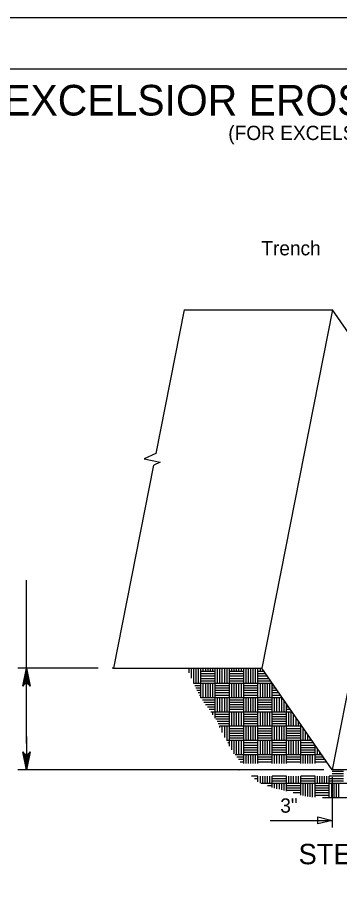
# Model space of a CAD drawing. Extents: x 1083.1 to 1117.1, y 719.4 to 741.4.
# Drawn here: x 1095.42 to 1098.57, y 732.69 to 741.35 of the extents above; entities that cross this region are included whole.
import ezdxf

# ---------------------------------------------------------------- set-up
doc = ezdxf.new("R2010")
doc.units = 0
for name, color, linetype in [('SH_Border', 7, 'Continuous'), ('SH_Cut_Line', 7, 'Continuous'), ('ST_Details', 7, 'Continuous'), ('ST_Text', 7, 'Continuous')]:
    doc.layers.add(name, color=color, linetype=linetype)

msp = doc.modelspace()

# ---------------------------------------------------------------- linework, layer by layer
at = {"layer": 'SH_Border'}
msp.add_lwpolyline([(1085.1264, 740.8541), (1116.6264, 740.8541), (1116.6264, 719.8541), (1085.1264, 719.8541)], close=True, dxfattribs=at)
at = {"layer": 'SH_Cut_Line'}
msp.add_lwpolyline([(1083.1264, 719.3541), (1117.1264, 719.3541), (1117.1264, 741.3541), (1083.1264, 741.3541)], close=True, dxfattribs=at)
at = {"layer": 'ST_Details'}
for p, q in [((1097.0496, 738.4926), (1096.7722, 737.0887)), ((1097.0496, 738.4926), (1098.5056, 738.4926)), ((1098.5056, 738.4926), (1097.8124, 734.9853)), ((1099.0136, 737.7593), (1098.5056, 738.4926)), ((1096.7721, 737.0886), (1096.6583, 737.0335)), ((1096.6576, 737.0352), (1096.8122, 737.0015)), ((1096.8122, 737.0015), (1096.7506, 736.9716)), ((1096.7491, 736.9719), (1096.3564, 734.9853)), ((1095.5022, 734.2481), (1095.5022, 735.846)), ((1098.7149, 735.0666), (1098.5021, 733.9896)), ((1096.2071, 734.9853), (1095.4163, 734.9853)), ((1095.4775, 734.8231), (1095.5022, 734.9853)), ((1095.4878, 734.8293), (1095.5022, 734.9853)), ((1095.5022, 734.8321), (1095.5022, 734.9853)), ((1095.5136, 734.8304), (1095.5022, 734.9853)), ((1095.5246, 734.825), (1095.5022, 734.9853)), ((1096.3564, 734.9853), (1096.3438, 734.9853)), ((1096.3564, 734.9853), (1097.8124, 734.9853)), ((1097.097, 734.9398), (1097.097, 734.9853)), ((1097.1203, 734.8873), (1097.1203, 734.9853)), ((1097.1436, 734.8359), (1097.1436, 734.9853)), ((1097.1669, 734.8359), (1097.1669, 734.9853)), ((1097.1902, 734.8359), (1097.1902, 734.9853)), ((1097.2136, 734.6952), (1097.2136, 734.9853)), ((1097.3535, 734.9524), (1097.2136, 734.9524)), ((1097.3535, 734.9291), (1097.2136, 734.9291)), ((1097.2369, 734.9524), (1097.2369, 734.9853)), ((1097.2602, 734.9524), (1097.2602, 734.9853)), ((1097.2836, 734.9524), (1097.2836, 734.9853)), ((1097.3069, 734.9524), (1097.3069, 734.9853)), ((1097.3301, 734.9524), (1097.3301, 734.9853)), ((1097.3535, 734.4967), (1097.3535, 734.9853)), ((1097.3768, 734.8359), (1097.3768, 734.9758)), ((1097.4001, 734.8359), (1097.4001, 734.9758)), ((1097.4235, 734.8359), (1097.4235, 734.9758)), ((1097.4468, 734.8359), (1097.4468, 734.9758)), ((1097.4701, 734.8359), (1097.4701, 734.9758)), ((1097.4934, 734.222), (1097.4934, 734.9853)), ((1097.6334, 734.9524), (1097.4934, 734.9524)), ((1097.6334, 734.9291), (1097.4934, 734.9291)), ((1097.5167, 734.9524), (1097.5167, 734.9853)), ((1097.5401, 734.9524), (1097.5401, 734.9853)), ((1097.5634, 734.9524), (1097.5634, 734.9853)), ((1097.5867, 734.9524), (1097.5867, 734.9853)), ((1097.6101, 734.9524), (1097.6101, 734.9853)), ((1097.6334, 734.0506), (1097.6334, 734.9853)), ((1097.6567, 734.8359), (1097.6567, 734.9853)), ((1097.68, 734.8359), (1097.68, 734.9853)), ((1097.7033, 734.8359), (1097.7033, 734.9853)), ((1097.7266, 734.8359), (1097.7266, 734.9853)), ((1097.75, 734.8359), (1097.75, 734.9853)), ((1097.7733, 734.0506), (1097.7733, 734.9853)), ((1097.8318, 734.9524), (1097.7733, 734.9524)), ((1097.8479, 734.9291), (1097.7733, 734.9291)), ((1097.7966, 734.9524), (1097.7966, 734.9853)), ((1098.5021, 733.9896), (1097.8124, 734.9853)), ((1097.9126, 734.8359), (1097.1431, 734.8359)), ((1097.3535, 734.9058), (1097.2136, 734.9058)), ((1097.3535, 734.8824), (1097.2136, 734.8824)), ((1097.3535, 734.8591), (1097.2136, 734.8591)), ((1097.2369, 734.7659), (1097.2369, 734.8359)), ((1097.2602, 734.7659), (1097.2602, 734.8359)), ((1097.2836, 734.7659), (1097.2836, 734.8359)), ((1097.3069, 734.7659), (1097.3069, 734.8359)), ((1097.3301, 734.7659), (1097.3301, 734.8359)), ((1097.6334, 734.9058), (1097.4934, 734.9058)), ((1097.6334, 734.8824), (1097.4934, 734.8824)), ((1097.6334, 734.8591), (1097.4934, 734.8591)), ((1097.5167, 734.7659), (1097.5167, 734.8359)), ((1097.5401, 734.7659), (1097.5401, 734.8359)), ((1097.5634, 734.7659), (1097.5634, 734.8359)), ((1097.5867, 734.7659), (1097.5867, 734.8359)), ((1097.6101, 734.7659), (1097.6101, 734.8359)), ((1097.8641, 734.9058), (1097.7733, 734.9058)), ((1097.8802, 734.8824), (1097.7733, 734.8824)), ((1097.8964, 734.8591), (1097.7733, 734.8591)), ((1097.7966, 734.7659), (1097.7966, 734.8359)), ((1097.82, 734.7659), (1097.82, 734.8359)), ((1097.8432, 734.7659), (1097.8432, 734.8359)), ((1097.8666, 734.7659), (1097.8666, 734.8359)), ((1097.8899, 734.7659), (1097.8899, 734.8359)), ((1097.9132, 734.0506), (1097.9132, 734.8349)), ((1097.2136, 734.8125), (1097.1536, 734.8125)), ((1097.2136, 734.7892), (1097.1639, 734.7892)), ((1097.2136, 734.7659), (1097.1743, 734.7659)), ((1097.2136, 734.7425), (1097.1871, 734.7425)), ((1097.2369, 734.6959), (1097.2369, 734.7659)), ((1097.2602, 734.6959), (1097.2602, 734.7659)), ((1097.2836, 734.6959), (1097.2836, 734.7659)), ((1097.3069, 734.6959), (1097.3069, 734.7659)), ((1097.3301, 734.6959), (1097.3301, 734.7659)), ((1097.4235, 734.8125), (1097.3535, 734.8125)), ((1097.4235, 734.7892), (1097.3535, 734.7892)), ((1097.4235, 734.7659), (1097.3535, 734.7659)), ((1097.4235, 734.7425), (1097.3535, 734.7425)), ((1097.4934, 734.8125), (1097.4235, 734.8125)), ((1097.4934, 734.7892), (1097.4235, 734.7892)), ((1097.4934, 734.7659), (1097.4235, 734.7659)), ((1097.4934, 734.7425), (1097.4235, 734.7425)), ((1097.5167, 734.6959), (1097.5167, 734.7659)), ((1097.5401, 734.6959), (1097.5401, 734.7659)), ((1097.5634, 734.6959), (1097.5634, 734.7659)), ((1097.5867, 734.6959), (1097.5867, 734.7659)), ((1097.6101, 734.6959), (1097.6101, 734.7659)), ((1097.7033, 734.8125), (1097.6334, 734.8125)), ((1097.7033, 734.7892), (1097.6334, 734.7892)), ((1097.7033, 734.7659), (1097.6334, 734.7659)), ((1097.7033, 734.7425), (1097.6334, 734.7425)), ((1097.7733, 734.8125), (1097.7033, 734.8125)), ((1097.7733, 734.7892), (1097.7033, 734.7892)), ((1097.7733, 734.7659), (1097.7033, 734.7659)), ((1097.7733, 734.7425), (1097.7033, 734.7425)), ((1097.7966, 734.6959), (1097.7966, 734.7659)), ((1097.82, 734.6959), (1097.82, 734.7659)), ((1097.8432, 734.6959), (1097.8432, 734.7659)), ((1097.8666, 734.6959), (1097.8666, 734.7659)), ((1097.8899, 734.6959), (1097.8899, 734.7659)), ((1097.9287, 734.8125), (1097.9132, 734.8125)), ((1097.9449, 734.7892), (1097.9132, 734.7892)), ((1097.961, 734.7659), (1097.9132, 734.7659)), ((1097.9771, 734.7425), (1097.9132, 734.7425)), ((1097.2136, 734.7192), (1097.1999, 734.7192)), ((1098.0095, 734.6959), (1097.2131, 734.6959)), ((1097.3535, 734.6726), (1097.2284, 734.6726)), ((1097.3535, 734.6493), (1097.2437, 734.6493)), ((1097.4235, 734.7192), (1097.3535, 734.7192)), ((1097.3768, 734.556), (1097.3768, 734.6959)), ((1097.4001, 734.556), (1097.4001, 734.6959)), ((1097.4934, 734.7192), (1097.4235, 734.7192)), ((1097.4235, 734.556), (1097.4235, 734.6959)), ((1097.4468, 734.556), (1097.4468, 734.6959)), ((1097.4701, 734.556), (1097.4701, 734.6959)), ((1097.6334, 734.6726), (1097.4934, 734.6726)), ((1097.6334, 734.6493), (1097.4934, 734.6493)), ((1097.7033, 734.7192), (1097.6334, 734.7192)), ((1097.6567, 734.556), (1097.6567, 734.6959)), ((1097.68, 734.556), (1097.68, 734.6959)), ((1097.7733, 734.7192), (1097.7033, 734.7192)), ((1097.7033, 734.556), (1097.7033, 734.6959)), ((1097.7266, 734.556), (1097.7266, 734.6959)), ((1097.75, 734.556), (1097.75, 734.6959)), ((1097.9132, 734.6726), (1097.7733, 734.6726)), ((1097.9132, 734.6493), (1097.7733, 734.6493)), ((1097.9832, 734.7192), (1097.9132, 734.7192)), ((1097.9366, 734.556), (1097.9366, 734.6959)), ((1097.9599, 734.556), (1097.9599, 734.6959)), ((1097.9933, 734.7192), (1097.9832, 734.7192)), ((1097.9832, 734.556), (1097.9832, 734.6959)), ((1098.0066, 734.556), (1098.0066, 734.6959)), ((1098.0298, 734.556), (1098.0298, 734.6665)), ((1097.3535, 734.6259), (1097.2599, 734.6259)), ((1097.3535, 734.6026), (1097.2771, 734.6026)), ((1097.3535, 734.5793), (1097.2944, 734.5793)), ((1097.6334, 734.6259), (1097.4934, 734.6259)), ((1097.6334, 734.6026), (1097.4934, 734.6026)), ((1097.6334, 734.5793), (1097.4934, 734.5793)), ((1097.9132, 734.6259), (1097.7733, 734.6259)), ((1097.9132, 734.6026), (1097.7733, 734.6026)), ((1097.9132, 734.5793), (1097.7733, 734.5793)), ((1098.0531, 734.0506), (1098.0531, 734.6328)), ((1098.0579, 734.6259), (1098.0531, 734.6259)), ((1098.0741, 734.6026), (1098.0531, 734.6026)), ((1098.0902, 734.5793), (1098.0531, 734.5793)), ((1098.1064, 734.556), (1097.3114, 734.556)), ((1097.3301, 734.5296), (1097.3301, 734.556)), ((1097.4235, 734.5327), (1097.3535, 734.5327)), ((1097.4235, 734.5094), (1097.3535, 734.5094)), ((1097.4235, 734.486), (1097.3603, 734.486)), ((1097.4934, 734.5327), (1097.4235, 734.5327)), ((1097.4934, 734.5094), (1097.4235, 734.5094)), ((1097.4934, 734.486), (1097.4235, 734.486)), ((1097.5167, 734.486), (1097.5167, 734.556)), ((1097.5167, 734.4161), (1097.5167, 734.486)), ((1097.5401, 734.486), (1097.5401, 734.556)), ((1097.5401, 734.4161), (1097.5401, 734.486)), ((1097.5634, 734.486), (1097.5634, 734.556)), ((1097.5634, 734.4161), (1097.5634, 734.486)), ((1097.5867, 734.486), (1097.5867, 734.556)), ((1097.5867, 734.4161), (1097.5867, 734.486)), ((1097.6101, 734.486), (1097.6101, 734.556)), ((1097.6101, 734.4161), (1097.6101, 734.486)), ((1097.7033, 734.5327), (1097.6334, 734.5327)), ((1097.7033, 734.5094), (1097.6334, 734.5094)), ((1097.7033, 734.486), (1097.6334, 734.486)), ((1097.7733, 734.5327), (1097.7033, 734.5327)), ((1097.7733, 734.5094), (1097.7033, 734.5094)), ((1097.7733, 734.486), (1097.7033, 734.486)), ((1097.7966, 734.486), (1097.7966, 734.556)), ((1097.7966, 734.4161), (1097.7966, 734.486)), ((1097.82, 734.486), (1097.82, 734.556)), ((1097.82, 734.4161), (1097.82, 734.486)), ((1097.8432, 734.486), (1097.8432, 734.556)), ((1097.8432, 734.4161), (1097.8432, 734.486)), ((1097.8666, 734.486), (1097.8666, 734.556)), ((1097.8666, 734.4161), (1097.8666, 734.486)), ((1097.8899, 734.486), (1097.8899, 734.556)), ((1097.8899, 734.4161), (1097.8899, 734.486)), ((1097.9832, 734.5327), (1097.9132, 734.5327)), ((1097.9832, 734.5094), (1097.9132, 734.5094)), ((1097.9832, 734.486), (1097.9132, 734.486)), ((1098.0531, 734.5327), (1097.9832, 734.5327)), ((1098.0531, 734.5094), (1097.9832, 734.5094)), ((1098.0531, 734.486), (1097.9832, 734.486)), ((1098.0765, 734.486), (1098.0765, 734.556)), ((1098.0765, 734.4161), (1098.0765, 734.486)), ((1098.0998, 734.486), (1098.0998, 734.556)), ((1098.0998, 734.4161), (1098.0998, 734.486)), ((1098.1231, 734.486), (1098.1231, 734.5319)), ((1098.1231, 734.4161), (1098.1231, 734.486)), ((1098.1465, 734.486), (1098.1465, 734.4981)), ((1098.1465, 734.4161), (1098.1465, 734.486)), ((1097.4235, 734.4627), (1097.3717, 734.4627)), ((1097.4235, 734.4394), (1097.3832, 734.4394)), ((1098.2033, 734.4161), (1097.3947, 734.4161)), ((1097.4001, 734.4051), (1097.4001, 734.4161)), ((1097.4934, 734.4627), (1097.4235, 734.4627)), ((1097.4934, 734.4394), (1097.4235, 734.4394)), ((1097.4235, 734.3559), (1097.4235, 734.4161)), ((1097.4468, 734.3062), (1097.4468, 734.4161)), ((1097.4701, 734.2761), (1097.4701, 734.4161)), ((1097.6334, 734.3928), (1097.4934, 734.3928)), ((1097.7033, 734.4627), (1097.6334, 734.4627)), ((1097.7033, 734.4394), (1097.6334, 734.4394)), ((1097.6567, 734.2761), (1097.6567, 734.4161)), ((1097.68, 734.2761), (1097.68, 734.4161)), ((1097.7733, 734.4627), (1097.7033, 734.4627)), ((1097.7733, 734.4394), (1097.7033, 734.4394)), ((1097.7033, 734.2761), (1097.7033, 734.4161)), ((1097.7266, 734.2761), (1097.7266, 734.4161)), ((1097.75, 734.2761), (1097.75, 734.4161)), ((1097.9132, 734.3928), (1097.7733, 734.3928)), ((1097.9832, 734.4627), (1097.9132, 734.4627)), ((1097.9832, 734.4394), (1097.9132, 734.4394)), ((1097.9366, 734.2761), (1097.9366, 734.4161)), ((1097.9599, 734.2761), (1097.9599, 734.4161)), ((1098.0531, 734.4627), (1097.9832, 734.4627)), ((1098.0531, 734.4394), (1097.9832, 734.4394)), ((1097.9832, 734.2761), (1097.9832, 734.4161)), ((1098.0066, 734.2761), (1098.0066, 734.4161)), ((1098.0298, 734.2761), (1098.0298, 734.4161)), ((1098.1931, 734.3928), (1098.0531, 734.3928)), ((1098.1698, 734.4161), (1098.1698, 734.4644)), ((1098.1931, 734.0506), (1098.1931, 734.4308)), ((1098.2164, 734.2761), (1098.2164, 734.3972)), ((1095.5022, 734.3148), (1095.5022, 734.0056)), ((1097.6334, 734.3694), (1097.4934, 734.3694)), ((1097.6334, 734.3461), (1097.4934, 734.3461)), ((1097.6334, 734.3228), (1097.4934, 734.3228)), ((1097.9132, 734.3694), (1097.7733, 734.3694)), ((1097.9132, 734.3461), (1097.7733, 734.3461)), ((1097.9132, 734.3228), (1097.7733, 734.3228)), ((1098.1931, 734.3694), (1098.0531, 734.3694)), ((1098.1931, 734.3461), (1098.0531, 734.3461)), ((1098.1931, 734.3228), (1098.0531, 734.3228)), ((1098.2397, 734.2761), (1098.2397, 734.3635)), ((1098.2631, 734.2761), (1098.2631, 734.3298)), ((1098.3002, 734.2761), (1097.4633, 734.2761)), ((1097.4934, 734.2529), (1097.4762, 734.2529)), ((1097.4934, 734.2295), (1097.4891, 734.2295)), ((1097.6334, 734.2994), (1097.4934, 734.2994)), ((1097.5167, 734.2062), (1097.5167, 734.2761)), ((1097.5401, 734.2062), (1097.5401, 734.2761)), ((1097.5634, 734.2062), (1097.5634, 734.2761)), ((1097.5867, 734.2062), (1097.5867, 734.2761)), ((1097.6101, 734.2062), (1097.6101, 734.2761)), ((1097.7033, 734.2529), (1097.6334, 734.2529)), ((1097.7033, 734.2295), (1097.6334, 734.2295)), ((1097.7733, 734.2529), (1097.7033, 734.2529)), ((1097.7733, 734.2295), (1097.7033, 734.2295)), ((1097.9132, 734.2994), (1097.7733, 734.2994)), ((1097.7966, 734.2062), (1097.7966, 734.2761)), ((1097.82, 734.2062), (1097.82, 734.2761)), ((1097.8432, 734.2062), (1097.8432, 734.2761)), ((1097.8666, 734.2062), (1097.8666, 734.2761)), ((1097.8899, 734.2062), (1097.8899, 734.2761)), ((1097.9832, 734.2529), (1097.9132, 734.2529)), ((1097.9832, 734.2295), (1097.9132, 734.2295)), ((1098.0531, 734.2529), (1097.9832, 734.2529)), ((1098.0531, 734.2295), (1097.9832, 734.2295)), ((1098.1931, 734.2994), (1098.0531, 734.2994)), ((1098.0765, 734.2062), (1098.0765, 734.2761)), ((1098.0998, 734.2062), (1098.0998, 734.2761)), ((1098.1231, 734.2062), (1098.1231, 734.2761)), ((1098.1465, 734.2062), (1098.1465, 734.2761)), ((1098.1698, 734.2062), (1098.1698, 734.2761)), ((1098.2631, 734.2529), (1098.1931, 734.2529)), ((1098.2631, 734.2295), (1098.1931, 734.2295)), ((1098.3164, 734.2529), (1098.2631, 734.2529)), ((1098.3326, 734.2295), (1098.2631, 734.2295)), ((1098.2864, 734.2761), (1098.2864, 734.2961)), ((1098.3331, 734.0506), (1098.3331, 734.2289)), ((1095.4798, 734.1499), (1095.5022, 733.9896)), ((1095.4909, 734.1444), (1095.5022, 733.9896)), ((1095.5271, 734.1518), (1095.5022, 733.9896)), ((1095.5166, 734.1456), (1095.5022, 733.9896)), ((1095.5022, 734.1428), (1095.5022, 733.9896)), ((1097.5167, 734.1848), (1097.5167, 734.2062)), ((1097.5401, 734.1475), (1097.5401, 734.2062)), ((1098.3971, 734.1362), (1097.5481, 734.1362)), ((1097.5634, 734.1362), (1097.5634, 734.2062)), ((1097.5867, 734.1362), (1097.5867, 734.2062)), ((1097.6101, 734.1362), (1097.6101, 734.2062)), ((1097.7033, 734.2062), (1097.6334, 734.2062)), ((1097.7033, 734.1829), (1097.6334, 734.1829)), ((1097.7033, 734.1595), (1097.6334, 734.1595)), ((1097.6567, 734.0506), (1097.6567, 734.1362)), ((1097.68, 734.0506), (1097.68, 734.1362)), ((1097.7733, 734.2062), (1097.7033, 734.2062)), ((1097.7733, 734.1829), (1097.7033, 734.1829)), ((1097.7733, 734.1595), (1097.7033, 734.1595)), ((1097.7033, 734.0506), (1097.7033, 734.1362)), ((1097.7266, 734.0506), (1097.7266, 734.1362)), ((1097.75, 734.0506), (1097.75, 734.1362)), ((1097.7966, 734.1362), (1097.7966, 734.2062)), ((1097.82, 734.1362), (1097.82, 734.2062)), ((1097.8432, 734.1362), (1097.8432, 734.2062)), ((1097.8666, 734.1362), (1097.8666, 734.2062)), ((1097.8899, 734.1362), (1097.8899, 734.2062)), ((1097.9832, 734.2062), (1097.9132, 734.2062)), ((1097.9832, 734.1829), (1097.9132, 734.1829)), ((1097.9832, 734.1595), (1097.9132, 734.1595)), ((1097.9366, 734.0506), (1097.9366, 734.1362)), ((1097.9599, 734.0506), (1097.9599, 734.1362)), ((1098.0531, 734.2062), (1097.9832, 734.2062)), ((1098.0531, 734.1829), (1097.9832, 734.1829)), ((1098.0531, 734.1595), (1097.9832, 734.1595)), ((1097.9832, 734.0506), (1097.9832, 734.1362)), ((1098.0066, 734.0506), (1098.0066, 734.1362)), ((1098.0298, 734.0506), (1098.0298, 734.1362)), ((1098.0765, 734.1362), (1098.0765, 734.2062)), ((1098.0998, 734.1362), (1098.0998, 734.2062)), ((1098.1231, 734.1362), (1098.1231, 734.2062)), ((1098.1465, 734.1362), (1098.1465, 734.2062)), ((1098.1698, 734.1362), (1098.1698, 734.2062)), ((1098.2631, 734.2062), (1098.1931, 734.2062)), ((1098.2631, 734.1829), (1098.1931, 734.1829)), ((1098.2631, 734.1595), (1098.1931, 734.1595)), ((1098.2164, 734.0506), (1098.2164, 734.1362)), ((1098.2397, 734.0506), (1098.2397, 734.1362)), ((1098.3331, 734.2062), (1098.2631, 734.2062)), ((1098.3331, 734.1829), (1098.2631, 734.1829)), ((1098.3331, 734.1595), (1098.2631, 734.1595)), ((1098.2631, 734.0506), (1098.2631, 734.1362)), ((1098.2864, 734.0506), (1098.2864, 734.1362)), ((1098.3097, 734.0506), (1098.3097, 734.1362)), ((1098.3564, 734.1362), (1098.3564, 734.1951)), ((1098.3796, 734.1362), (1098.3796, 734.1614)), ((1097.6334, 734.1129), (1097.5651, 734.1129)), ((1097.6334, 734.0896), (1097.5821, 734.0896)), ((1097.6334, 734.0663), (1097.5997, 734.0663)), ((1097.9132, 734.1129), (1097.7733, 734.1129)), ((1097.9132, 734.0896), (1097.7733, 734.0896)), ((1097.9132, 734.0663), (1097.7733, 734.0663)), ((1098.1931, 734.1129), (1098.0531, 734.1129)), ((1098.1931, 734.0896), (1098.0531, 734.0896)), ((1098.1931, 734.0663), (1098.0531, 734.0663)), ((1098.4133, 734.1129), (1098.3331, 734.1129)), ((1098.4295, 734.0896), (1098.3331, 734.0896)), ((1098.4456, 734.0663), (1098.3331, 734.0663)), ((1098.4187, 733.9896), (1095.4163, 733.9896)), ((1097.5865, 733.9896), (1097.5876, 733.9897)), ((1098.5429, 733.973), (1098.5006, 733.973)), ((1098.7618, 733.9896), (1098.5021, 733.9896)), ((1098.6129, 733.973), (1098.5429, 733.973)), ((1097.7733, 733.9264), (1097.7108, 733.9264)), ((1097.7733, 733.903), (1097.7385, 733.903)), ((1097.7733, 733.8797), (1097.7661, 733.8797)), ((1097.7733, 733.8737), (1097.7733, 733.9287)), ((1097.7966, 733.9264), (1097.7966, 733.9287)), ((1097.7966, 733.8595), (1097.7966, 733.9264)), ((1097.82, 733.9264), (1097.82, 733.9287)), ((1097.82, 733.8564), (1097.82, 733.9264)), ((1097.8432, 733.9264), (1097.8432, 733.9287)), ((1097.8432, 733.8564), (1097.8432, 733.9264)), ((1097.8666, 733.9264), (1097.8666, 733.9287)), ((1097.8666, 733.8564), (1097.8666, 733.9264)), ((1097.8899, 733.9264), (1097.8899, 733.9287)), ((1097.8899, 733.8564), (1097.8899, 733.9264)), ((1097.9132, 733.8175), (1097.9132, 733.9287)), ((1097.9832, 733.9264), (1097.9132, 733.9264)), ((1097.9832, 733.903), (1097.9132, 733.903)), ((1097.9832, 733.8797), (1097.9132, 733.8797)), ((1098.0531, 733.9264), (1097.9832, 733.9264)), ((1098.0531, 733.903), (1097.9832, 733.903)), ((1098.0531, 733.8797), (1097.9832, 733.8797)), ((1098.0531, 733.7805), (1098.0531, 733.9287)), ((1098.0765, 733.9264), (1098.0765, 733.9287)), ((1098.0765, 733.8564), (1098.0765, 733.9264)), ((1098.0998, 733.9264), (1098.0998, 733.9287)), ((1098.0998, 733.8564), (1098.0998, 733.9264)), ((1098.1231, 733.9264), (1098.1231, 733.9287)), ((1098.1231, 733.8564), (1098.1231, 733.9264)), ((1098.1465, 733.9264), (1098.1465, 733.9287)), ((1098.1465, 733.8564), (1098.1465, 733.9264)), ((1098.1698, 733.9264), (1098.1698, 733.9287)), ((1098.1698, 733.8564), (1098.1698, 733.9264)), ((1098.1931, 733.7434), (1098.1931, 733.9287)), ((1098.2631, 733.9264), (1098.1931, 733.9264)), ((1098.2631, 733.903), (1098.1931, 733.903)), ((1098.2631, 733.8797), (1098.1931, 733.8797)), ((1098.3331, 733.9264), (1098.2631, 733.9264)), ((1098.3331, 733.903), (1098.2631, 733.903)), ((1098.3331, 733.8797), (1098.2631, 733.8797)), ((1098.3331, 733.7219), (1098.3331, 733.9287)), ((1098.3564, 733.9264), (1098.3564, 733.9287)), ((1098.3564, 733.8564), (1098.3564, 733.9264)), ((1098.3796, 733.9264), (1098.3796, 733.9287)), ((1098.3796, 733.8564), (1098.3796, 733.9264)), ((1098.403, 733.9264), (1098.403, 733.9287)), ((1098.403, 733.8564), (1098.403, 733.9264)), ((1098.4263, 733.9264), (1098.4263, 733.9287)), ((1098.4263, 733.8564), (1098.4263, 733.9264)), ((1098.4496, 733.9264), (1098.4496, 733.9287)), ((1098.4496, 733.8564), (1098.4496, 733.9264)), ((1098.473, 733.7115), (1098.473, 733.9287)), ((1098.5429, 733.9264), (1098.473, 733.9264)), ((1098.5429, 733.903), (1098.473, 733.903)), ((1098.5429, 733.8797), (1098.473, 733.8797)), ((1098.5429, 733.9497), (1098.5006, 733.9497)), ((1098.5021, 733.9196), (1098.5021, 733.4252)), ((1098.6129, 733.9497), (1098.5429, 733.9497)), ((1098.6129, 733.9264), (1098.5429, 733.9264)), ((1098.6129, 733.903), (1098.5429, 733.903)), ((1098.6129, 733.8797), (1098.5429, 733.8797)), ((1099.5942, 733.8564), (1097.805, 733.8564)), ((1097.9132, 733.8331), (1097.8661, 733.8331)), ((1097.9366, 733.8114), (1097.9366, 733.8564)), ((1097.9599, 733.8052), (1097.9599, 733.8564)), ((1097.9832, 733.799), (1097.9832, 733.8564)), ((1098.0066, 733.7929), (1098.0066, 733.8564)), ((1098.0298, 733.7867), (1098.0298, 733.8564)), ((1098.1931, 733.8331), (1098.0531, 733.8331)), ((1098.1931, 733.8098), (1098.0531, 733.8098)), ((1098.1931, 733.7864), (1098.0531, 733.7864)), ((1098.2164, 733.7373), (1098.2164, 733.8564)), ((1098.2397, 733.7311), (1098.2397, 733.8564)), ((1098.2631, 733.7272), (1098.2631, 733.8564)), ((1098.2864, 733.7254), (1098.2864, 733.8564)), ((1098.3097, 733.7237), (1098.3097, 733.8564)), ((1098.473, 733.8331), (1098.3331, 733.8331)), ((1098.473, 733.8098), (1098.3331, 733.8098)), ((1098.473, 733.7864), (1098.3331, 733.7864)), ((1098.4963, 733.7164), (1098.4963, 733.8564)), ((1098.5196, 733.7164), (1098.5196, 733.8564)), ((1098.5429, 733.7164), (1098.5429, 733.8564)), ((1098.5662, 733.7164), (1098.5662, 733.8564)), ((1098.1931, 733.7631), (1098.1189, 733.7631)), ((1098.473, 733.7631), (1098.3331, 733.7631)), ((1098.473, 733.7398), (1098.3331, 733.7398)), ((1098.7943, 733.7164), (1098.4068, 733.7164)), ((1098.4263, 733.7149), (1098.4263, 733.7164)), ((1098.4496, 733.7132), (1098.4496, 733.7164)), ((1097.8928, 733.4952), (1098.5021, 733.4952))]:
    msp.add_line(p, q, dxfattribs=at)
for points in [[(1095.4668, 734.8083), (1095.5022, 734.9853), (1095.5376, 734.8083)], [(1095.5376, 734.1666), (1095.5022, 733.9896), (1095.4668, 734.1666)]]:
    msp.add_lwpolyline(points, dxfattribs=at)
msp.add_lwpolyline([(1098.3621, 733.5302), (1098.5021, 733.4952), (1098.3621, 733.4602)], close=True, dxfattribs=at)
for centre, start, end in [((1095.5023, 734.794), 22.08782, 157.91395), ((1095.5022, 734.1809), 202.08782, 337.91395)]:
    msp.add_arc(centre, 0.0382, start, end, dxfattribs=at)

# ---------------------------------------------------------------- texts
at = {"layer": 'ST_Text'}
for s, height, p in [('NON-EXCELSIOR EROSION CONTROL MAT INSTALLATION', 0.3, (1094.2488, 740.3963)), ('(FOR EXCELSIOR EROSION CONTROL MATS, SEE BELOW)', 0.14, (1097.4819, 740.156)), ('Trench', 0.14, (1097.8061, 739.0272)), ('3"', 0.14, (1097.992, 733.57)), ('STEP 1', 0.2, (1098.1718, 733.0652))]:
    msp.add_text(s, height=height, dxfattribs=at).set_placement(p)

doc.saveas('drawing.dxf')
